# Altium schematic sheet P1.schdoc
size 297 x 209 mm; Symbol: Drawing-Symbol_A4; @Project Name: Reflectle; @Page Count: 1; @Update Date: 2026-10-31; @Create Date: 2026-10-31; @Schematic Name: Schematic1; @Page No: 1; @Page Name: P1; Company: EasyEDA.com; Version: V1.0; Page Size: A4; Device: Drawing-Symbol_A4; @Create Time: 22:04:22; @Update Time: 22:04:22; Border: 1; Width: 1170; Height: 825; Region Start: 1; X Region Count: 6; Y Region Count: 4; Blade Width: 10; Title Block Position: 3; @Board Name: Board1
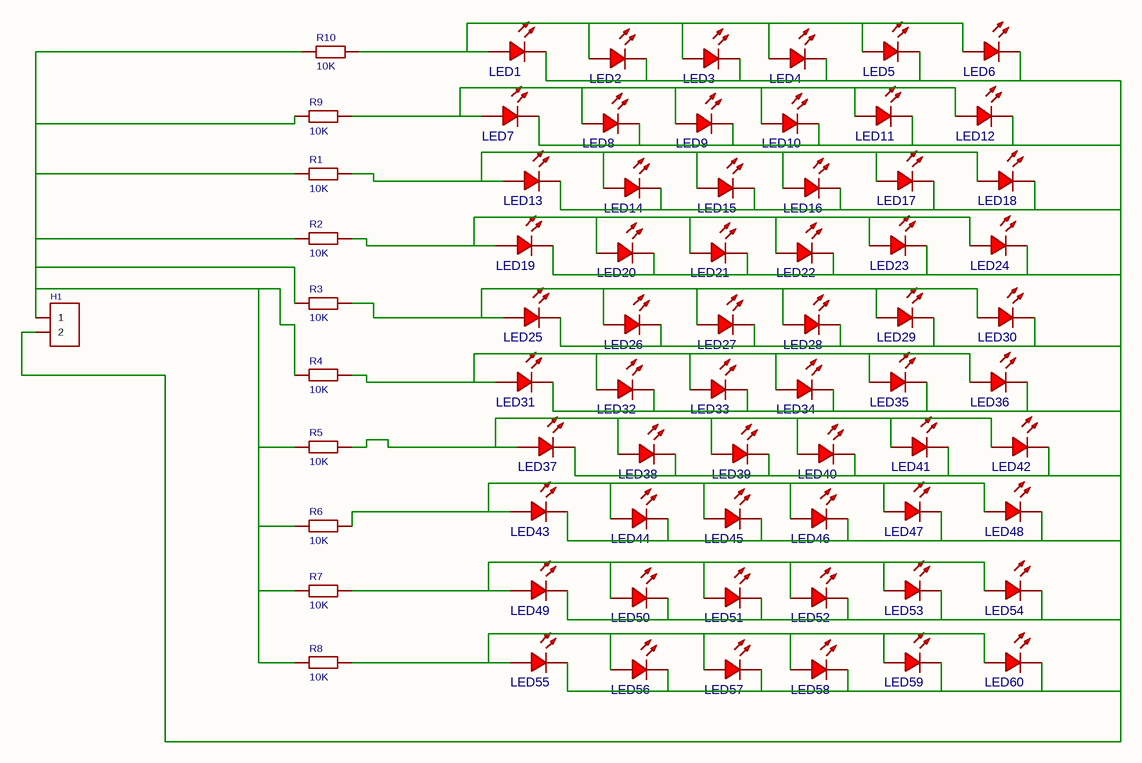
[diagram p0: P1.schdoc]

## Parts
H1  (no value)  [HDR-TH_2P-P2.54-V-F]
LED1  (no value)  [LED0402-RD_YELLOW]
LED2  (no value)  [LED0402-RD_YELLOW]
LED3  (no value)  [LED0402-RD_YELLOW]
LED4  (no value)  [LED0402-RD_YELLOW]
LED5  (no value)  [LED0402-RD_YELLOW]
LED6  (no value)  [LED0402-RD_YELLOW]
LED7  (no value)  [LED0402-RD_YELLOW]
LED8  (no value)  [LED0402-RD_YELLOW]
LED9  (no value)  [LED0402-RD_YELLOW]
LED10  (no value)  [LED0402-RD_YELLOW]
LED11  (no value)  [LED0402-RD_YELLOW]
LED12  (no value)  [LED0402-RD_YELLOW]
LED13  (no value)  [LED0402-RD_YELLOW]
LED14  (no value)  [LED0402-RD_YELLOW]
LED15  (no value)  [LED0402-RD_YELLOW]
LED16  (no value)  [LED0402-RD_YELLOW]
LED17  (no value)  [LED0402-RD_YELLOW]
LED18  (no value)  [LED0402-RD_YELLOW]
LED19  (no value)  [LED0402-RD_YELLOW]
LED20  (no value)  [LED0402-RD_YELLOW]
LED21  (no value)  [LED0402-RD_YELLOW]
LED22  (no value)  [LED0402-RD_YELLOW]
LED23  (no value)  [LED0402-RD_YELLOW]
LED24  (no value)  [LED0402-RD_YELLOW]
LED25  (no value)  [LED0402-RD_YELLOW]
LED26  (no value)  [LED0402-RD_YELLOW]
LED27  (no value)  [LED0402-RD_YELLOW]
LED28  (no value)  [LED0402-RD_YELLOW]
LED29  (no value)  [LED0402-RD_YELLOW]
LED30  (no value)  [LED0402-RD_YELLOW]
LED31  (no value)  [LED0402-RD_YELLOW]
LED32  (no value)  [LED0402-RD_YELLOW]
LED33  (no value)  [LED0402-RD_YELLOW]
LED34  (no value)  [LED0402-RD_YELLOW]
LED35  (no value)  [LED0402-RD_YELLOW]
LED36  (no value)  [LED0402-RD_YELLOW]
LED37  (no value)  [LED0402-RD_YELLOW]
LED38  (no value)  [LED0402-RD_YELLOW]
LED39  (no value)  [LED0402-RD_YELLOW]
LED40  (no value)  [LED0402-RD_YELLOW]
LED41  (no value)  [LED0402-RD_YELLOW]
LED42  (no value)  [LED0402-RD_YELLOW]
LED43  (no value)  [LED0402-RD_YELLOW]
LED44  (no value)  [LED0402-RD_YELLOW]
LED45  (no value)  [LED0402-RD_YELLOW]
LED46  (no value)  [LED0402-RD_YELLOW]
LED47  (no value)  [LED0402-RD_YELLOW]
LED48  (no value)  [LED0402-RD_YELLOW]
LED49  (no value)  [LED0402-RD_YELLOW]
LED50  (no value)  [LED0402-RD_YELLOW]
LED51  (no value)  [LED0402-RD_YELLOW]
LED52  (no value)  [LED0402-RD_YELLOW]
LED53  (no value)  [LED0402-RD_YELLOW]
LED54  (no value)  [LED0402-RD_YELLOW]
LED55  (no value)  [LED0402-RD_YELLOW]
LED56  (no value)  [LED0402-RD_YELLOW]
LED57  (no value)  [LED0402-RD_YELLOW]
LED58  (no value)  [LED0402-RD_YELLOW]
LED59  (no value)  [LED0402-RD_YELLOW]
LED60  (no value)  [LED0402-RD_YELLOW]
R1  10K  [R0603]
R2  10K  [R0603]
R3  10K  [R0603]
R4  10K  [R0603]
R5  10K  [R0603]
R6  10K  [R0603]
R7  10K  [R0603]
R8  10K  [R0603]
R9  10K  [R0603]
R10  10K  [R0603]

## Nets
NetH1_1: H1.1 R1.1 R2.1 R3.1 R4.1 R5.1 R6.1 R7.1 R8.1 R9.1 R10.1
NetH1_2: H1.2 LED1.2(C) LED2.2(C) LED3.2(C) LED4.2(C) LED5.2(C) LED6.2(C) LED7.2(C) LED8.2(C) LED9.2(C) LED10.2(C) LED11.2(C) LED12.2(C) LED13.2(C) LED14.2(C) LED15.2(C) LED16.2(C) LED17.2(C) LED18.2(C) LED19.2(C) LED20.2(C) LED21.2(C) LED22.2(C) LED23.2(C) LED24.2(C) LED25.2(C) LED26.2(C) LED27.2(C) LED28.2(C) LED29.2(C) LED30.2(C) LED31.2(C) LED32.2(C) LED33.2(C) LED34.2(C) LED35.2(C) LED36.2(C) LED37.2(C) LED38.2(C) LED39.2(C) LED40.2(C) LED41.2(C) LED42.2(C) LED43.2(C) LED44.2(C) LED45.2(C) LED46.2(C) LED47.2(C) LED48.2(C) LED49.2(C) LED50.2(C) LED51.2(C) LED52.2(C) LED53.2(C) LED54.2(C) LED55.2(C) LED56.2(C) LED57.2(C) LED58.2(C) LED59.2(C) LED60.2(C)
NetLED1_1: LED1.1(A) LED2.1(A) LED3.1(A) LED4.1(A) LED5.1(A) LED6.1(A) R10.2
NetLED7_1: LED7.1(A) LED8.1(A) LED9.1(A) LED10.1(A) LED11.1(A) LED12.1(A) R9.2
NetLED13_1: LED13.1(A) LED14.1(A) LED15.1(A) LED16.1(A) LED17.1(A) LED18.1(A) R1.2
NetLED19_1: LED19.1(A) LED20.1(A) LED21.1(A) LED22.1(A) LED23.1(A) LED24.1(A) R2.2
NetLED25_1: LED25.1(A) LED26.1(A) LED27.1(A) LED28.1(A) LED29.1(A) LED30.1(A) R3.2
NetLED31_1: LED31.1(A) LED32.1(A) LED33.1(A) LED34.1(A) LED35.1(A) LED36.1(A) R4.2
NetLED37_1: LED37.1(A) LED38.1(A) LED39.1(A) LED40.1(A) LED41.1(A) LED42.1(A) R5.2
NetLED43_1: LED43.1(A) LED44.1(A) LED45.1(A) LED46.1(A) LED47.1(A) LED48.1(A) R6.2
NetLED49_1: LED49.1(A) LED50.1(A) LED51.1(A) LED52.1(A) LED53.1(A) LED54.1(A) R7.2
NetLED55_1: LED55.1(A) LED56.1(A) LED57.1(A) LED58.1(A) LED59.1(A) LED60.1(A) R8.2

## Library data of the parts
H1 = HDR-F_2.54_1x2P: Manufacturer: BOOMELE(博穆精密); Manufacturer Part: 2.54-1*2P母; Symbol: Header-Female-2.54_1x2; ConvertToPcb: yes; ModelId: 925d5dffa823422895d76d9dc6f5e8cd0819f05c4eef4c71ace90d822a990e87; ModelName: HDR-TH_2P-P2.54-F-LI-1X2P; ModelTransform: 215.7476,98.425,0,0,0,0,0,0,-129.921
LED1-LED60 = LED_0402-R: Symbol: LED_R; ConvertToPcb: yes; ModelId: 8310098dd8ce4c639f83193eb655c2a50819f05c4eef4c71ace90d822a990e87; ModelTransform: 40.1574,19.685,0,0,0,0,0,0,0
R1-R10 = Res_0603: Symbol: Res; ConvertToPcb: yes; ModelId: 112863783b5b41f1b5254f87eedc79320819f05c4eef4c71ace90d822a990e87; ModelTransform: 31.8897,63.7794,0,90,0,0,0,0,0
